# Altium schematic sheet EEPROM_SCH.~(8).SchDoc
size D
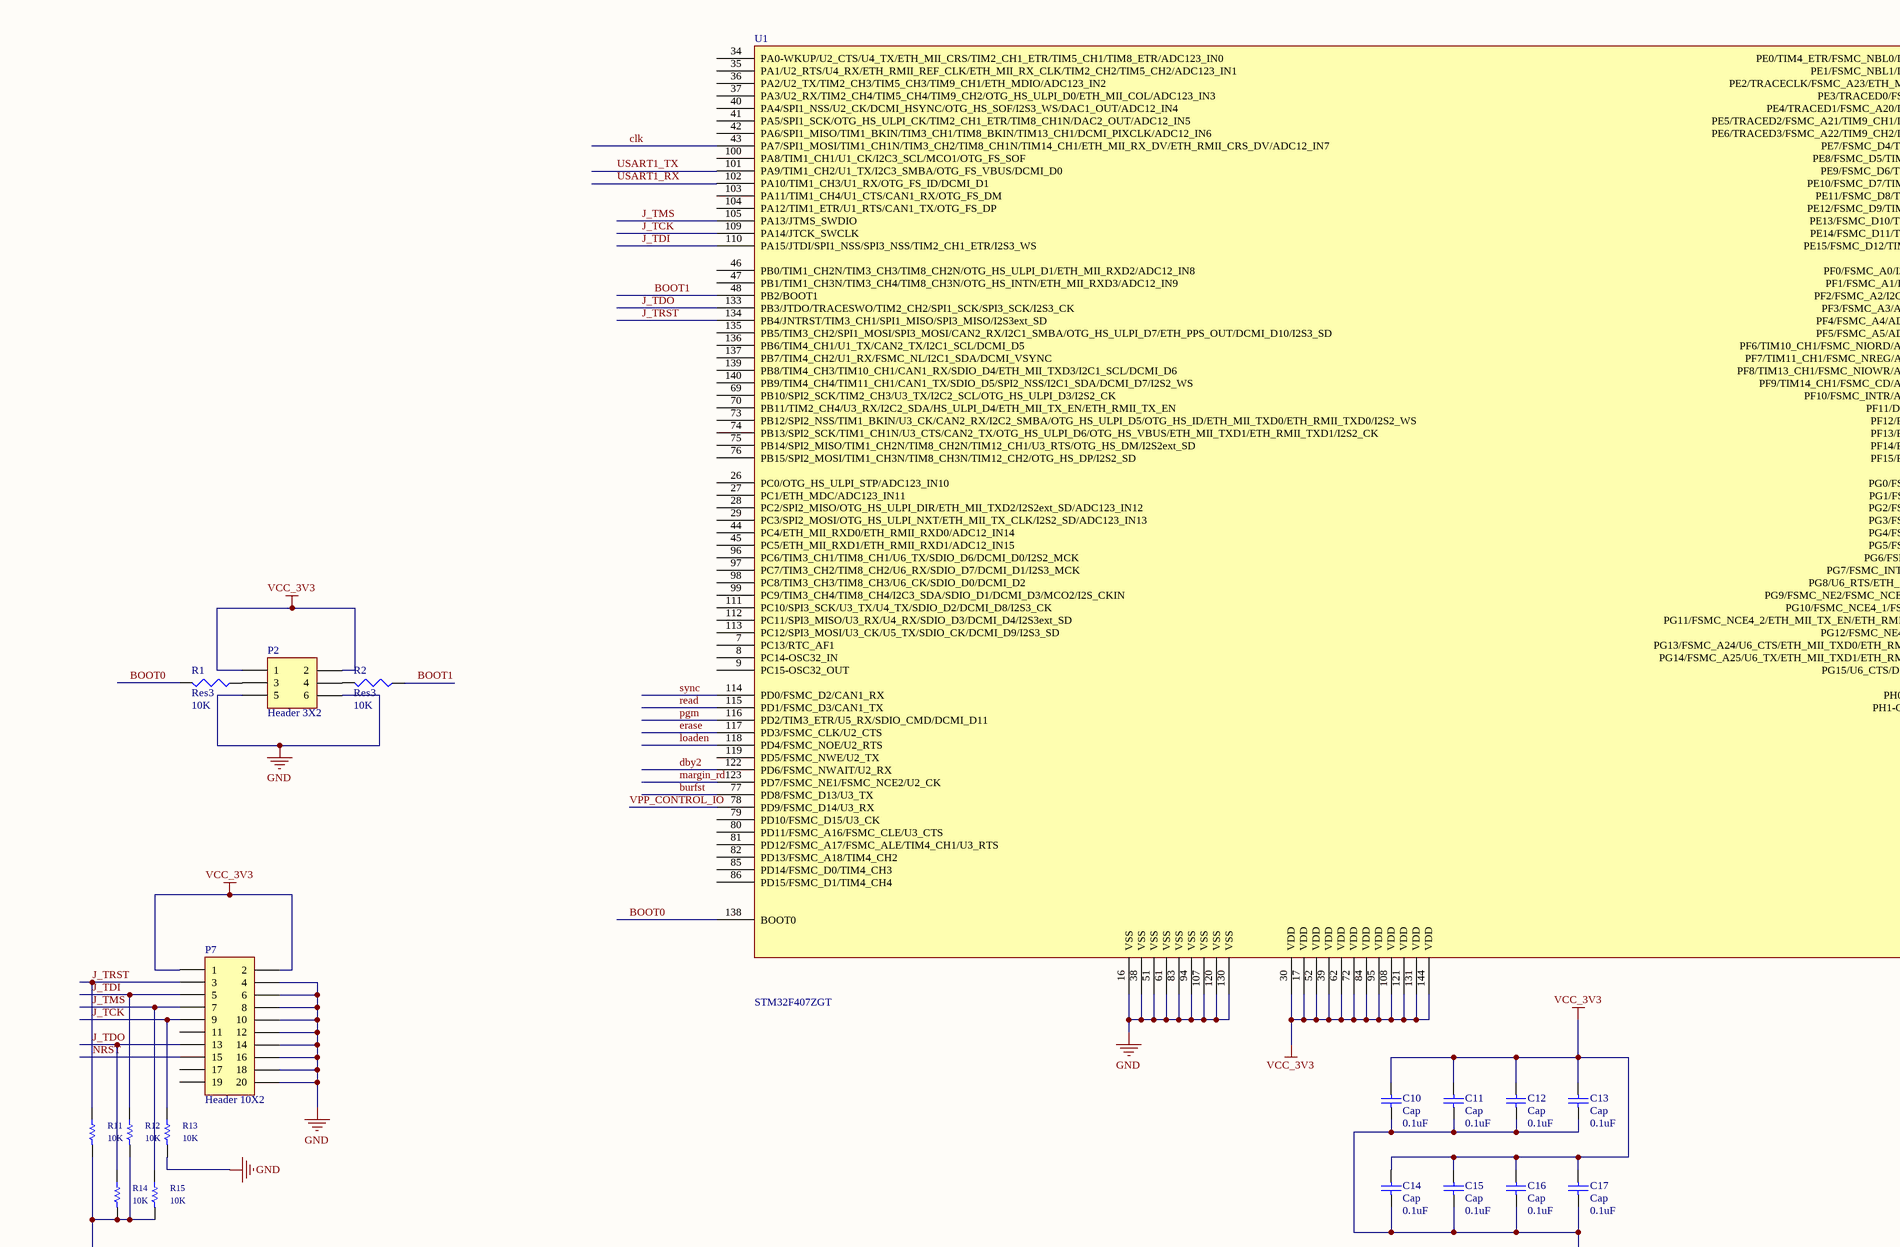
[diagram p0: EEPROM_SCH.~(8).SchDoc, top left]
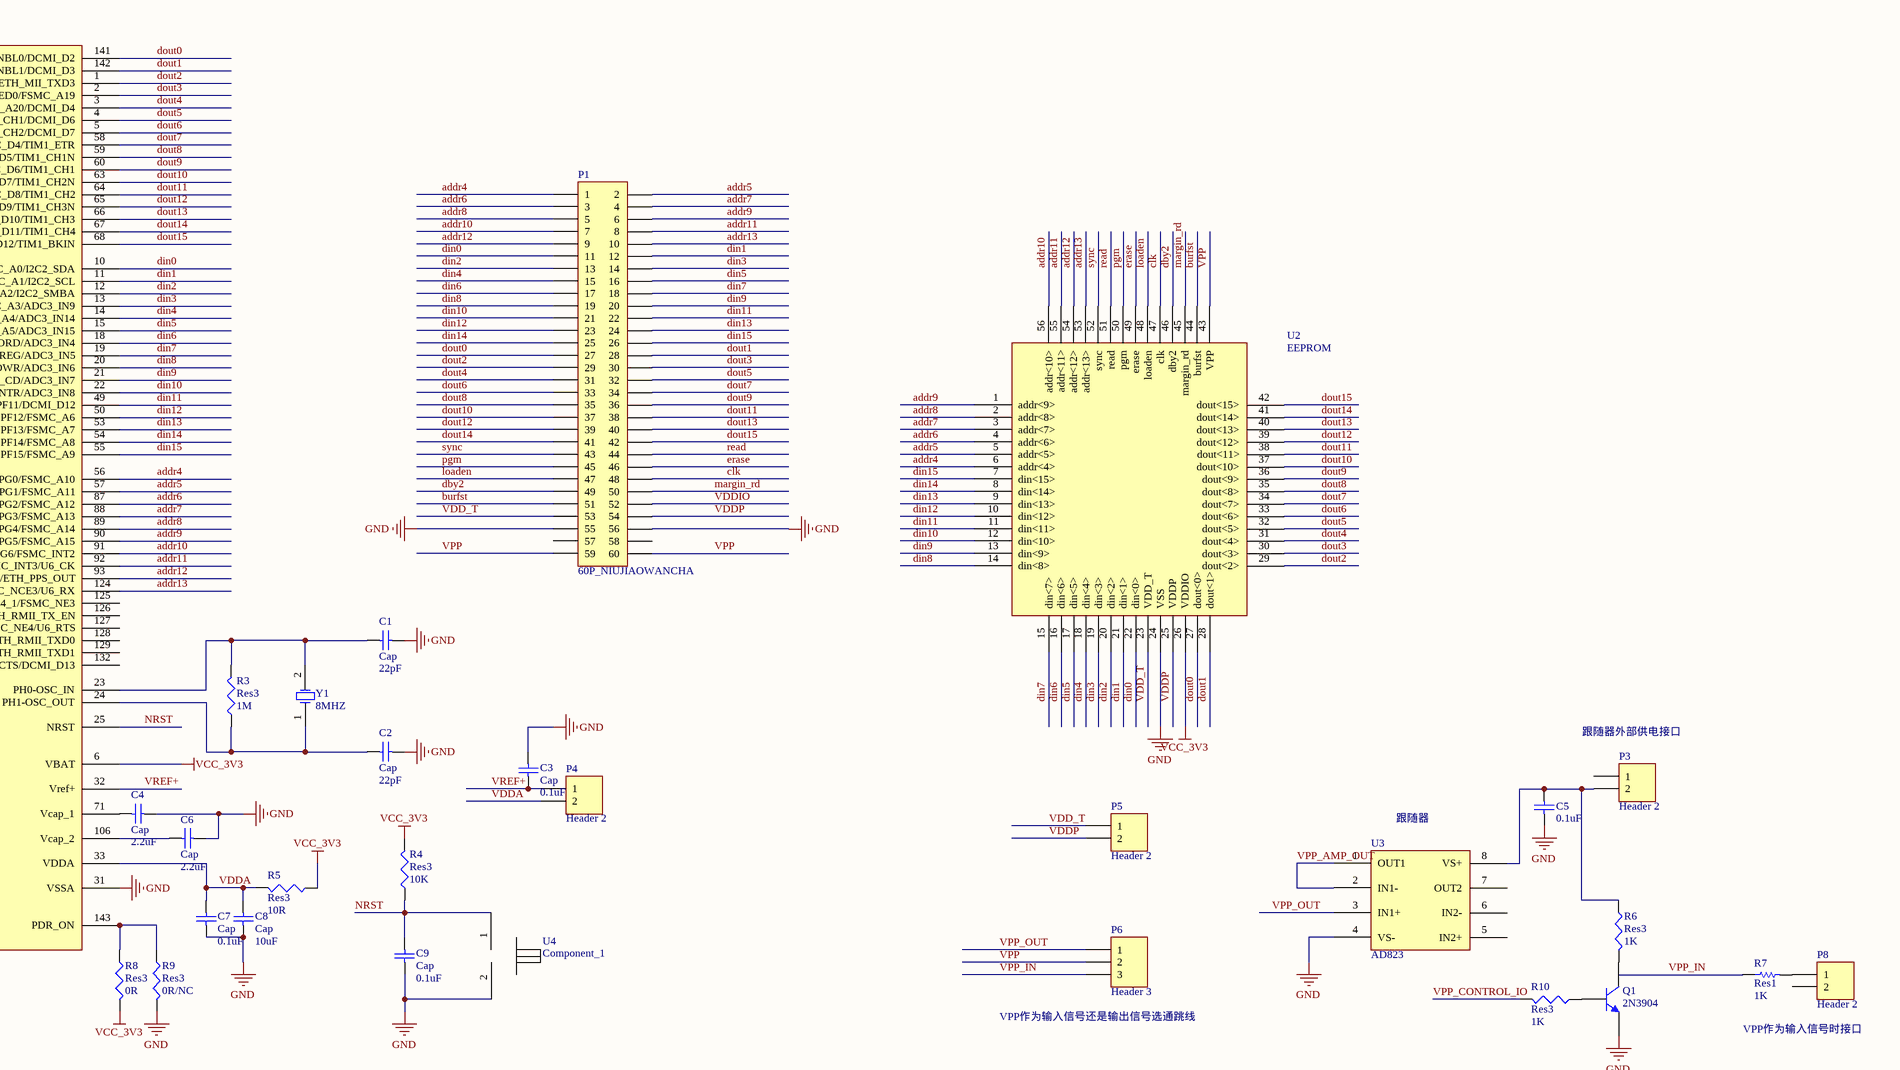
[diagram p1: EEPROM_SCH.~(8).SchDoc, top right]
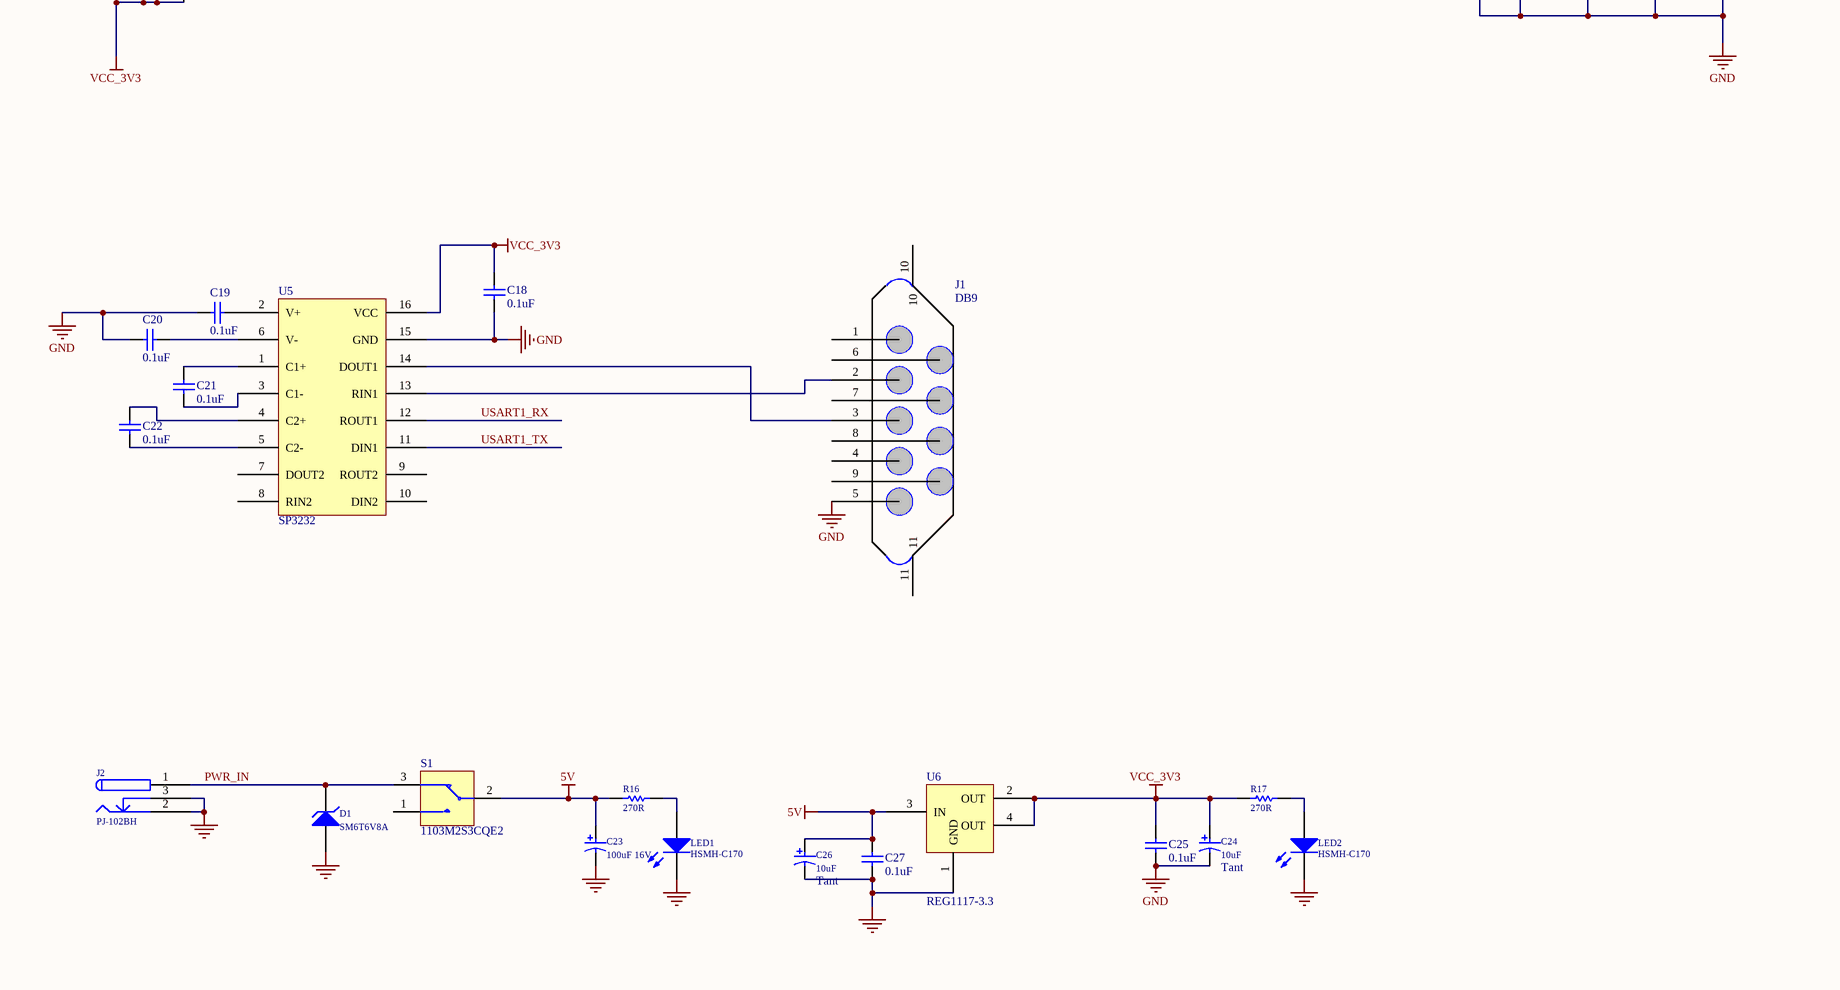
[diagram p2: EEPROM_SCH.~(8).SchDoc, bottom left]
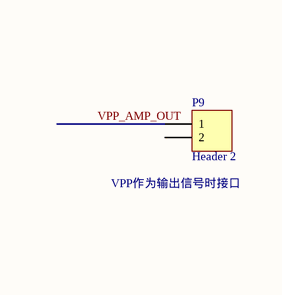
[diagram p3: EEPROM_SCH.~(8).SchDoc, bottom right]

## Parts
C1  Cap  value 22pF  [RAD-0.3]
C2  Cap  value 22pF  [RAD-0.3]
C3  Cap  value 0.1uF  [RAD-0.3]
C4  Cap  value 2.2uF  [RAD-0.3]
C5  0.1uF  [CC2012-0805]
C6  Cap  value 2.2uF  [RAD-0.3]
C7  Cap  value 0.1uF  [RAD-0.3]
C8  Cap  value 10uF  [RAD-0.3]
C9  Cap  value 0.1uF  [RAD-0.3]
C10  Cap  value 0.1uF  [RAD-0.3]
C11  Cap  value 0.1uF  [RAD-0.3]
C12  Cap  value 0.1uF  [RAD-0.3]
C13  Cap  value 0.1uF  [RAD-0.3]
C14  Cap  value 0.1uF  [RAD-0.3]
C15  Cap  value 0.1uF  [RAD-0.3]
C16  Cap  value 0.1uF  [RAD-0.3]
C17  Cap  value 0.1uF  [RAD-0.3]
C18  0.1uF  [CC2012-0805]
C19  0.1uF  [CC2012-0805]
C20  0.1uF  [CC2012-0805]
C21  0.1uF  [CC2012-0805]
C22  0.1uF  [CC2012-0805]
C23  100uF 16V  [CAPPR2-5X6.8]
C24  10uF  Capacitor Type: Tant  [MCCT-B]
C25  0.1uF  [CC2012-0805]
C26  10uF  Capacitor Type: Tant  [MCCT-B]
C27  0.1uF  [CC2012-0805]
D1  SM6T6V8A  [PCBComponent_1]
J1  DB9  [PCBComponent_1]
J2  PJ-102BH  [PCBComponent_1]
LED1  HSMH-C170  [SMD _LED]
LED2  HSMH-C170  [SMD _LED]
P1  60P_NIUJIAOWANCHA  [PCBComponent_1]
P2  Header 3X2  [PCBComponent_1]
P3  Header 2  [HDR1X2]
P4  Header 2  [HDR1X2]
P5  Header 2  [HDR1X2]
P6  Header 3  [HDR1X3]
P7  Header 10X2  [HDR2X10]
P8  Header 2  [HDR1X2]
P9  Header 2  [HDR1X2]
Q1  2N3904  [TO-92A]
R1  Res3  value 10K  [J1-0603]
R2  Res3  value 10K  [J1-0603]
R3  Res3  value 1M  [J1-0603]
R4  Res3  value 10K  [J1-0603]
R5  Res3  value 10R  [J1-0603]
R6  Res3  value 1K  [J1-0603]
R7  Res1  value 1K  [AXIAL-0.3]
R8  Res3  value 0R  [J1-0603]
R9  Res3  value 0R/NC  [J1-0603]
R10  Res3  value 1K  [J1-0603]
R11  10K  [CC2012-0805]
R12  10K  [CC2012-0805]
R13  10K  [CC2012-0805]
R14  10K  [CC2012-0805]
R15  10K  [CC2012-0805]
R16  270R  [CR2012-0805]
R17  270R  [CR2012-0805]
S1  1103M2S3CQE2  [PCBComponent_1]
U1  STM32F407ZGT  [STM32F407ZGT6_LCC144]
U2  EEPROM
U3  AD823  [PCBComponent_1]
U4  Component_1
U5  SP3232
U6  REG1117-3.3  [PCBComponent_1]
Y1  8MHZ  [R38]

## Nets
5V: C23.1 C26.1 C27.2 R16.2 S1.2 U6.3(IN)
GND: C1.1 C2.1 C3.1 C4.2 C5.1 C6.2 C7.2 C8.2 C9.2 C10.1 C11.1 C12.1 C13.1 C14.1 C15.1 C16.1 C17.1 C18.1 C19.1 C20.2 C23.2 C24.2 C25.1 C26.2 C27.1 D1.1(A) J1.5 J2.2 J2.3 LED1.2(K) LED2.2(K) P1.55 P1.56 P2.5 P2.6 P7.4 P7.6 P7.8 P7.10 P7.12 P7.14 P7.16 P7.18 P7.20 Q1.1(E) R9.2 R13.2 U1.16(VSS) U1.31(VSSA) U1.38(VSS) U1.51(VSS) U1.61(VSS) U1.83(VSS) U1.94(VSS) U1.107(VSS) U1.120(VSS) U1.130(VSS) U2.24(VSS) U3.4(VS-) U4.2 U5.15(GND) U6.1(GND)
VCC_3V3: C10.2 C11.2 C12.2 C13.2 C14.2 C15.2 C16.2 C17.2 C18.2 C24.1 C25.2 P2.1 P2.2 P7.1 P7.2 R4.2 R5.1 R8.2 R11.2 R12.2 R14.2 R15.2 R17.2 U1.6(VBAT) U1.17(VDD) U1.30(VDD) U1.39(VDD) U1.52(VDD) U1.62(VDD) U1.72(VDD) U1.84(VDD) U1.95(VDD) U1.108(VDD) U1.121(VDD) U1.131(VDD) U1.144(VDD) U2.26(VDDIO) U5.16(VCC) U6.2(OUT) U6.4(OUT)
addr4: P1.1 U1.56(PG0/FSMC_A10) U2.6(addr<4>)
addr5: P1.2 U1.57(PG1/FSMC_A11) U2.5(addr<5>)
addr6: P1.3 U1.87(PG2/FSMC_A12) U2.4(addr<6>)
addr7: P1.4 U1.88(PG3/FSMC_A13) U2.3(addr<7>)
addr8: P1.5 U1.89(PG4/FSMC_A14) U2.2(addr<8>)
addr9: P1.6 U1.90(PG5/FSMC_A15) U2.1(addr<9>)
addr10: P1.7 U1.91(PG6/FSMC_INT2) U2.56(addr<10>)
addr11: P1.8 U1.92(PG7/FSMC_INT3/U6_CK) U2.55(addr<11>)
addr12: P1.9 U1.93(PG8/U6_RTS/ETH_PPS_OUT) U2.54(addr<12>)
addr13: P1.10 U1.124(PG9/FSMC_NE2/FSMC_NCE3/U6_RX) U2.53(addr<13>)
BOOT0: R1.2 U1.138(BOOT0)
BOOT1: R2.1 U1.48(PB2/BOOT1)
burfst: P1.51 U1.77(PD8/FSMC_D13/U3_TX) U2.44(burfst)
clk: P1.48 U1.43(PA7/SPI1_MOSI/TIM1_CH1N/TIM3_CH2/TIM8_CH1N/TIM14_CH1/ETH_MII_RX_DV/ETH_RMII_CRS_DV/ADC12_IN7) U2.47(clk)
dby2: P1.49 U1.122(PD6/FSMC_NWAIT/U2_RX) U2.46(dby2)
din0: P1.11 U1.10(PF0/FSMC_A0/I2C2_SDA) U2.22(din<0>)
din1: P1.12 U1.11(PF1/FSMC_A1/I2C2_SCL) U2.21(din<1>)
din2: P1.13 U1.12(PF2/FSMC_A2/I2C2_SMBA) U2.20(din<2>)
din3: P1.14 U1.13(PF3/FSMC_A3/ADC3_IN9) U2.19(din<3>)
din4: P1.15 U1.14(PF4/FSMC_A4/ADC3_IN14) U2.18(din<4>)
din5: P1.16 U1.15(PF5/FSMC_A5/ADC3_IN15) U2.17(din<5>)
din6: P1.17 U1.18(PF6/TIM10_CH1/FSMC_NIORD/ADC3_IN4) U2.16(din<6>)
din7: P1.18 U1.19(PF7/TIM11_CH1/FSMC_NREG/ADC3_IN5) U2.15(din<7>)
din8: P1.19 U1.20(PF8/TIM13_CH1/FSMC_NIOWR/ADC3_IN6) U2.14(din<8>)
din9: P1.20 U1.21(PF9/TIM14_CH1/FSMC_CD/ADC3_IN7) U2.13(din<9>)
din10: P1.21 U1.22(PF10/FSMC_INTR/ADC3_IN8) U2.12(din<10>)
din11: P1.22 U1.49(PF11/DCMI_D12) U2.11(din<11>)
din12: P1.23 U1.50(PF12/FSMC_A6) U2.10(din<12>)
din13: P1.24 U1.53(PF13/FSMC_A7) U2.9(din<13>)
din14: P1.25 U1.54(PF14/FSMC_A8) U2.8(din<14>)
din15: P1.26 U1.55(PF15/FSMC_A9) U2.7(din<15>)
dout0: P1.27 U1.141(PE0/TIM4_ETR/FSMC_NBL0/DCMI_D2) U2.27(dout<0>)
dout1: P1.28 U1.142(PE1/FSMC_NBL1/DCMI_D3) U2.28(dout<1>)
dout2: P1.29 U1.1(PE2/TRACECLK/FSMC_A23/ETH_MII_TXD3) U2.29(dout<2>)
dout3: P1.30 U1.2(PE3/TRACED0/FSMC_A19) U2.30(dout<3>)
dout4: P1.31 U1.3(PE4/TRACED1/FSMC_A20/DCMI_D4) U2.31(dout<4>)
dout5: P1.32 U1.4(PE5/TRACED2/FSMC_A21/TIM9_CH1/DCMI_D6) U2.32(dout<5>)
dout6: P1.33 U1.5(PE6/TRACED3/FSMC_A22/TIM9_CH2/DCMI_D7) U2.33(dout<6>)
dout7: P1.34 U1.58(PE7/FSMC_D4/TIM1_ETR) U2.34(dout<7>)
dout8: P1.35 U1.59(PE8/FSMC_D5/TIM1_CH1N) U2.35(dout<8>)
dout9: P1.36 U1.60(PE9/FSMC_D6/TIM1_CH1) U2.36(dout<9>)
dout10: P1.37 U1.63(PE10/FSMC_D7/TIM1_CH2N) U2.37(dout<10>)
dout11: P1.38 U1.64(PE11/FSMC_D8/TIM1_CH2) U2.38(dout<11>)
dout12: P1.39 U1.65(PE12/FSMC_D9/TIM1_CH3N) U2.39(dout<12>)
dout13: P1.40 U1.66(PE13/FSMC_D10/TIM1_CH3) U2.40(dout<13>)
dout14: P1.41 U1.67(PE14/FSMC_D11/TIM1_CH4) U2.41(dout<14>)
dout15: P1.42 U1.68(PE15/FSMC_D12/TIM1_BKIN) U2.42(dout<15>)
erase: P1.46 U1.117(PD3/FSMC_CLK/U2_CTS) U2.49(erase)
J_TCK: C9.1 P7.3 P7.5 P7.7 P7.9 P7.13 P7.15 R4.1 R11.1 R12.1 R13.1 R14.1 R15.1 U1.25(NRST) U1.105(PA13/JTMS_SWDIO) U1.109(PA14/JTCK_SWCLK) U1.110(PA15/JTDI/SPI1_NSS/SPI3_NSS/TIM2_CH1_ETR/I2S3_WS) U1.133(PB3/JTDO/TRACESWO/TIM2_CH2/SPI1_SCK/SPI3_SCK/I2S3_CK) U1.134(PB4/JNTRST/TIM3_CH1/SPI1_MISO/SPI3_MISO/I2S3ext_SD) U4.1  [also labelled J_TDI, J_TDO, J_TMS, J_TRST, NRST]
loaden: P1.47 U1.118(PD4/FSMC_NOE/U2_RTS) U2.48(loaden)
margin_rd: P1.50 U1.123(PD7/FSMC_NE1/FSMC_NCE2/U2_CK) U2.45(margin_rd)
pgm: P1.45 U1.116(PD2/TIM3_ETR/U5_RX/SDIO_CMD/DCMI_D11) U2.50(pgm)
PWR_IN: D1.2(K) J2.1 S1.3
read: P1.44 U1.115(PD1/FSMC_D3/CAN1_TX) U2.51(read)
sync: P1.43 U1.114(PD0/FSMC_D2/CAN1_RX) U2.52(sync)
USART1_RX: U1.102(PA10/TIM1_CH3/U1_RX/OTG_FS_ID/DCMI_D1) U5.12(ROUT1)
USART1_TX: U1.101(PA9/TIM1_CH2/U1_TX/I2C3_SMBA/OTG_FS_VBUS/DCMI_D0) U5.11(DIN1)
VDD_T: P1.53 P5.1 U2.23(VDD_T)
VDDA: C7.1 C8.1 P4.2 R5.2 U1.33(VDDA)
VDDIO: P1.52
VDDP: P1.54 P5.2 U2.25(VDDP)
VPP: P1.59 P1.60 P6.2 U2.43(VPP)
VPP_AMP_OUT: P9.1 U3.1(OUT1) U3.2(IN1-)
VPP_CONTROL_IO: R10.2 U1.78(PD9/FSMC_D14/U3_RX)
VPP_IN: P6.3 R7.1
VPP_OUT: P6.1 U3.3(IN1+)
VREF+: C3.2 P4.1 U1.32(Vref+)
NetC1_2: C1.2 R3.2 U1.23(PH0-OSC_IN) Y1.2(OSC2)
NetC2_2: C2.2 R3.1 U1.24(PH1-OSC_OUT) Y1.1(OSC1)
NetC4_1: C4.1 U1.71(Vcap_1)
NetC5_2: C5.2 P3.2 R6.1 U3.8(VS+)
NetC6_1: C6.1 U1.106(Vcap_2)
NetC19_2: C19.2 U5.2(V+)
NetC20_1: C20.1 U5.6(V-)
NetC21_1: C21.1 U5.3(C1-)
NetC21_2: C21.2 U5.1(C1+)
NetC22_1: C22.1 U5.5(C2-)
NetC22_2: C22.2 U5.4(C2+)
NetJ1_2: J1.2 U5.13(RIN1)
NetJ1_3: J1.3 U5.14(DOUT1)
NetLED1_1: LED1.1(A) R16.1
NetLED2_1: LED2.1(A) R17.1
NetP2_3: P2.3 R1.1
NetP2_4: P2.4 R2.2
NetP8_1: P8.1 R7.2
NetQ1_2: Q1.2(B) R10.1
NetQ1_3: Q1.3(C) R6.2
NetR8_1: R8.1 R9.1 U1.143(PDR_ON)

Not connected (* = marked no-connect by the designer): J1 1 4 6 7 8 9 10 11; P1 57 58; P3 1; P7 11 17 19; P8 2; P9 2; S1 1; U1 7(PC13/RTC_AF1) 8(PC14-OSC32_IN) 9(PC15-OSC32_OUT) 26(PC0/OTG_HS_ULPI_STP/ADC123_IN10) 27(PC1/ETH_MDC/ADC123_IN11) 28(PC2/SPI2_MISO/OTG_HS_ULPI_DIR/ETH_MII_TXD2/I2S2ext_SD/ADC123_IN12) 29(PC3/SPI2_MOSI/OTG_HS_ULPI_NXT/ETH_MII_TX_CLK/I2S2_SD/ADC123_IN13) 34(PA0-WKUP/U2_CTS/U4_TX/ETH_MII_CRS/TIM2_CH1_ETR/TIM5_CH1/TIM8_ETR/ADC123_IN0) 35(PA1/U2_RTS/U4_RX/ETH_RMII_REF_CLK/ETH_MII_RX_CLK/TIM2_CH2/TIM5_CH2/ADC123_IN1) 36(PA2/U2_TX/TIM2_CH3/TIM5_CH3/TIM9_CH1/ETH_MDIO/ADC123_IN2) 37(PA3/U2_RX/TIM2_CH4/TIM5_CH4/TIM9_CH2/OTG_HS_ULPI_D0/ETH_MII_COL/ADC123_IN3) 40(PA4/SPI1_NSS/U2_CK/DCMI_HSYNC/OTG_HS_SOF/I2S3_WS/DAC1_OUT/ADC12_IN4) 41(PA5/SPI1_SCK/OTG_HS_ULPI_CK/TIM2_CH1_ETR/TIM8_CH1N/DAC2_OUT/ADC12_IN5) 42(PA6/SPI1_MISO/TIM1_BKIN/TIM3_CH1/TIM8_BKIN/TIM13_CH1/DCMI_PIXCLK/ADC12_IN6) 44(PC4/ETH_MII_RXD0/ETH_RMII_RXD0/ADC12_IN14) 45(PC5/ETH_MII_RXD1/ETH_RMII_RXD1/ADC12_IN15) 46(PB0/TIM1_CH2N/TIM3_CH3/TIM8_CH2N/OTG_HS_ULPI_D1/ETH_MII_RXD2/ADC12_IN8) 47(PB1/TIM1_CH3N/TIM3_CH4/TIM8_CH3N/OTG_HS_INTN/ETH_MII_RXD3/ADC12_IN9) 69(PB10/SPI2_SCK/TIM2_CH3/U3_TX/I2C2_SCL/OTG_HS_ULPI_D3/I2S2_CK) 70(PB11/TIM2_CH4/U3_RX/I2C2_SDA/HS_ULPI_D4/ETH_MII_TX_EN/ETH_RMII_TX_EN) 73(PB12/SPI2_NSS/TIM1_BKIN/U3_CK/CAN2_RX/I2C2_SMBA/OTG_HS_ULPI_D5/OTG_HS_ID/ETH_MII_TXD0/ETH_RMII_TXD0/I2S2_WS) 74(PB13/SPI2_SCK/TIM1_CH1N/U3_CTS/CAN2_TX/OTG_HS_ULPI_D6/OTG_HS_VBUS/ETH_MII_TXD1/ETH_RMII_TXD1/I2S2_CK) 75(PB14/SPI2_MISO/TIM1_CH2N/TIM8_CH2N/TIM12_CH1/U3_RTS/OTG_HS_DM/I2S2ext_SD) 76(PB15/SPI2_MOSI/TIM1_CH3N/TIM8_CH3N/TIM12_CH2/OTG_HS_DP/I2S2_SD) 79(PD10/FSMC_D15/U3_CK) 80(PD11/FSMC_A16/FSMC_CLE/U3_CTS) 81(PD12/FSMC_A17/FSMC_ALE/TIM4_CH1/U3_RTS) 82(PD13/FSMC_A18/TIM4_CH2) 85(PD14/FSMC_D0/TIM4_CH3) 86(PD15/FSMC_D1/TIM4_CH4) 96(PC6/TIM3_CH1/TIM8_CH1/U6_TX/SDIO_D6/DCMI_D0/I2S2_MCK) 97(PC7/TIM3_CH2/TIM8_CH2/U6_RX/SDIO_D7/DCMI_D1/I2S3_MCK) 98(PC8/TIM3_CH3/TIM8_CH3/U6_CK/SDIO_D0/DCMI_D2) 99(PC9/TIM3_CH4/TIM8_CH4/I2C3_SDA/SDIO_D1/DCMI_D3/MCO2/I2S_CKIN) 100(PA8/TIM1_CH1/U1_CK/I2C3_SCL/MCO1/OTG_FS_SOF) 103(PA11/TIM1_CH4/U1_CTS/CAN1_RX/OTG_FS_DM) 104(PA12/TIM1_ETR/U1_RTS/CAN1_TX/OTG_FS_DP) 111(PC10/SPI3_SCK/U3_TX/U4_TX/SDIO_D2/DCMI_D8/I2S3_CK) 112(PC11/SPI3_MISO/U3_RX/U4_RX/SDIO_D3/DCMI_D4/I2S3ext_SD) 113(PC12/SPI3_MOSI/U3_CK/U5_TX/SDIO_CK/DCMI_D9/I2S3_SD) 119(PD5/FSMC_NWE/U2_TX) 125(PG10/FSMC_NCE4_1/FSMC_NE3) 126(PG11/FSMC_NCE4_2/ETH_MII_TX_EN/ETH_RMII_TX_EN) 127(PG12/FSMC_NE4/U6_RTS) 128(PG13/FSMC_A24/U6_CTS/ETH_MII_TXD0/ETH_RMII_TXD0) 129(PG14/FSMC_A25/U6_TX/ETH_MII_TXD1/ETH_RMII_TXD1) 132(PG15/U6_CTS/DCMI_D13) 135(PB5/TIM3_CH2/SPI1_MOSI/SPI3_MOSI/CAN2_RX/I2C1_SMBA/OTG_HS_ULPI_D7/ETH_PPS_OUT/DCMI_D10/I2S3_SD) 136(PB6/TIM4_CH1/U1_TX/CAN2_TX/I2C1_SCL/DCMI_D5) 137(PB7/TIM4_CH2/U1_RX/FSMC_NL/I2C1_SDA/DCMI_VSYNC) 139(PB8/TIM4_CH3/TIM10_CH1/CAN1_RX/SDIO_D4/ETH_MII_TXD3/I2C1_SCL/DCMI_D6) 140(PB9/TIM4_CH4/TIM11_CH1/CAN1_TX/SDIO_D5/SPI2_NSS/I2C1_SDA/DCMI_D7/I2S2_WS); U3 5(IN2+) 6(IN2-) 7(OUT2); U5 7(DOUT2) 8(RIN2) 9(ROUT2) 10(DIN2)

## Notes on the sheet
- (near P3) 跟随器外部供电接口
- (near U3) 跟随器
- (near P6) VPP作为输入信号还是输出信号选通跳线
- VPP作为输入信号时接口
- (near P9) VPP作为输出信号时接口

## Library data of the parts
C1-C4 C6-C17 = Cap: Capacitor
C5 C18-C22 C25 C27 = CAP: Capacitor
C23 = CAP_POLAR_1: Polar Capacitor
C24 C26 = CAP_POLAR: Polar Capacitor; AEMS Code: 2100110
D1 = BZG03C13: Zener Diode, 6.2V, 5W; Manufacturer: Microsemi
J1 U1-U3 U5 U6 = Component_1
J2 = KLD-0202-B: Low Voltage Power Supply Connector; Manufacturer: Kycon; AEMS Code: 3510211
LED1 LED2 = HSMX-C670: Typical RED GaAs SMD LED Agilent make; AEMS Code: 2610081
P1 = Header 30X2: Header, 30-Pin, Dual row
P2 = Header 3X2: Header, 3-Pin, Dual row
P3-P5 P8 P9 = Header 2: Header, 2-Pin
P6 = Header 3: Header, 3-Pin
P7 = Header 10X2: Header, 10-Pin, Dual row
Q1 = 2N3904: NPN General Purpose Amplifier
R1-R6 R8-R10 = Res3: Resistor
R7 = Res1: Resistor
R11-R15 = RES: Resistor; AEMS Code: 1200012JT
R16 R17 = RES: Resistor; AEMS Code: 1200430
S1 = PCB_MOUNT_SWITCH: SPDT Subminiature Toggle Switch
Y1 = XTAL: Crystal Oscillator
